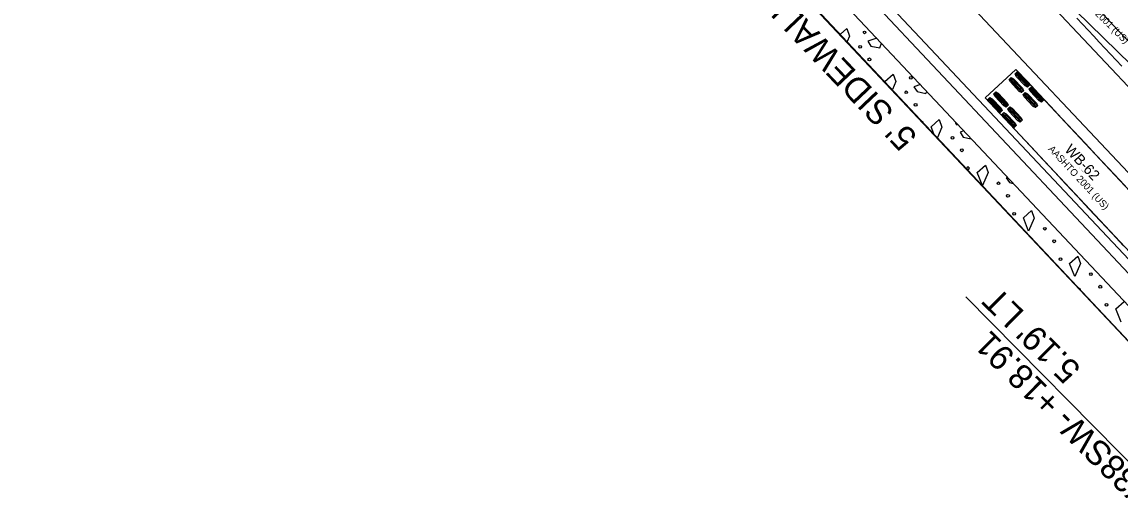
# Model space of a CAD drawing. Extents: x 1262642 to 1268358, y 767825 to 773481.
# Drawn here: x 1266385.4 to 1266608.5, y 772120.2 to 772219.4 of the extents above; entities that cross this region are included whole.
import ezdxf

# ---------------------------------------------------------------- set-up
doc = ezdxf.new("R2010")
doc.units = 0
for name, color, linetype in [('Prop Conc 2ft 6in Curb and Gutter', 7, 'Continuous'), ('Prop Conc 4in Sidewalk', 7, 'Continuous'), ('Prop Dimension Text', 7, 'Continuous'), ('Prop EOT', 7, 'Continuous'), ('Prop Horizontal Alignment', 7, 'Continuous'), ('Prop Lane Lines', 7, 'Continuous'), ('Prop Paved Shoulder', 7, 'Continuous'), ('Prop Shade Light', 7, 'Continuous'), ('Scratch_Level_3', 7, 'Continuous')]:
    doc.layers.add(name, color=color, linetype=linetype)

msp = doc.modelspace()

# ---------------------------------------------------------------- linework, layer by layer
at = {"layer": 'Prop Conc 2ft 6in Curb and Gutter'}
for p, q in [((1266506.17, 772278.96), (1266647.88, 772128.24)), ((1266502.71, 772276.07), (1266644.44, 772125.33)), ((1266497.36, 772274.9), (1266640.83, 772121.86)), ((1266551.72, 772216.91), (1266553.03, 772218.07)), ((1266553.03, 772218.07), (1266553.55, 772216.54)), ((1266553.55, 772216.54), (1266553.09, 772215.46)), ((1266559.09, 772216.11), (1266557.25, 772215.49)), ((1266557.25, 772215.49), (1266557.89, 772214.5)), ((1266559.7, 772214.13), (1266560.05, 772215.08)), ((1266557.89, 772214.5), (1266559.7, 772214.13)), ((1266560.72, 772207.33), (1266562.41, 772208.83)), ((1266562.41, 772208.83), (1266562.93, 772207.29)), ((1266560.74, 772207.3), (1266560.72, 772207.33)), ((1266562.93, 772207.29), (1266562.25, 772205.69)), ((1266567.94, 772206.69), (1266566.63, 772206.24)), ((1266566.63, 772206.24), (1266567.28, 772205.26)), ((1266567.28, 772205.26), (1266569.08, 772204.88)), ((1266569.08, 772204.88), (1266569.24, 772205.31)), ((1266570.11, 772198.08), (1266571.79, 772199.58)), ((1266571.79, 772199.58), (1266572.32, 772198.05)), ((1266570.66, 772196.71), (1266570.11, 772198.08)), ((1266572.32, 772198.05), (1266571.41, 772195.92)), ((1266576.8, 772197.26), (1266576.02, 772197)), ((1266576.02, 772197), (1266576.66, 772196.01)), ((1266576.66, 772196.01), (1266578.3, 772195.67)), ((1266579.49, 772188.84), (1266581.18, 772190.34)), ((1266581.18, 772190.34), (1266581.7, 772188.8)), ((1266580.57, 772186.16), (1266579.49, 772188.84)), ((1266581.7, 772188.8), (1266580.57, 772186.16)), ((1266585.66, 772187.84), (1266585.4, 772187.75)), ((1266585.4, 772187.75), (1266586.05, 772186.77)), ((1266586.05, 772186.77), (1266586.82, 772186.61)), ((1266588.87, 772179.59), (1266590.56, 772181.09)), ((1266589.95, 772176.91), (1266588.87, 772179.59)), ((1266591.08, 772179.56), (1266589.95, 772176.91)), ((1266590.56, 772181.09), (1266591.08, 772179.56)), ((1266598.26, 772170.35), (1266599.94, 772171.84)), ((1266599.34, 772167.67), (1266598.26, 772170.35)), ((1266600.47, 772170.31), (1266599.34, 772167.67)), ((1266599.94, 772171.84), (1266600.47, 772170.31)), ((1266607.64, 772161.1), (1266609.33, 772162.6)), ((1266608.72, 772158.42), (1266607.64, 772161.1))]:
    msp.add_line(p, q, dxfattribs=at)
for centre, radius in [((1266556.62, 772217.3), 0.268), ((1266555.69, 772214.37), 0.268), ((1266557.59, 772211.82), 0.292), ((1266566, 772208.06), 0.268), ((1266565.08, 772205.12), 0.268), ((1266566.98, 772202.57), 0.292), ((1266574.46, 772195.88), 0.268), ((1266576.36, 772193.33), 0.292), ((1266583.84, 772186.63), 0.268), ((1266585.75, 772184.08), 0.292), ((1266587.01, 772180.42), 0.268), ((1266593.23, 772177.39), 0.268), ((1266595.13, 772174.84), 0.292), ((1266596.4, 772171.18), 0.268), ((1266602.61, 772168.14), 0.268), ((1266604.51, 772165.59), 0.292), ((1266605.78, 772161.93), 0.268)]:
    msp.add_circle(centre, radius, dxfattribs=at)
for centre, radius, start, end in [((1266562.64, 772212.72), 0.289, 200.6053, 245.8613), ((1266568.25, 772198.91), 0.268, 25.7051, 60.5975), ((1266575.38, 772198.81), 0.268, 138.6088, 307.8579), ((1266577.63, 772189.67), 0.268, 230.5683, 215.7344), ((1266600.23, 772164.96), 0.268, 344.2878, 102.0149)]:
    msp.add_arc(centre, radius, start, end, dxfattribs=at)
at = {"layer": 'Prop Conc 4in Sidewalk'}
for p, q in [((1266502.44, 772276.36), (1266644.6, 772125.15)), ((1266498.39, 772273.36), (1266640.96, 772121.73))]:
    msp.add_line(p, q, dxfattribs=at)
at = {"layer": 'Prop Dimension Text'}
msp.add_line((1266577.15, 772163.56), (1266617.63, 772122.52), dxfattribs=at)
at = {"layer": 'Prop EOT'}
msp.add_line((1266507.71, 772280.24), (1266649.33, 772129.6), dxfattribs=at)
msp.add_arc((1266840.27, 772443.46), 318.09, 223.2333, 243.6532, dxfattribs=at)
at = {"layer": 'Prop Horizontal Alignment'}
msp.add_line((1266456.7, 772369.54), (1266660.64, 772152.62), dxfattribs=at)
at = {"layer": 'Prop Lane Lines'}
msp.add_line((1266516.45, 772288.46), (1266651.9, 772144.4), dxfattribs=at)
msp.add_arc((1275047.31, 780021.23), 11427, 216.367499, 223.547684, dxfattribs=at)
at = {"layer": 'Prop Paved Shoulder'}
msp.add_arc((1275047.31, 780021.23), 11449, 220.505091, 223.202447, dxfattribs=at)
at = {"layer": 'Prop Shade Light'}
msp.add_arc((1275047.31, 780021.23), 11449, 220.505091, 223.202447, dxfattribs=at)
at = {"layer": 'Scratch_Level_3'}
for p, q in [((1266584.3, 772236.71), (1266618.52, 772203.06)), ((1266587.35, 772209.79), (1266581.14, 772203.99)), ((1266588.88, 772205.4), (1266586.38, 772208.08)), ((1266589.75, 772206.22), (1266587.25, 772208.89)), ((1266620.13, 772174.72), (1266587.35, 772209.79)), ((1266589.92, 772206.37), (1266587.42, 772209.05)), ((1266590.09, 772206.53), (1266587.58, 772209.21)), ((1266588.55, 772205.09), (1266586.04, 772207.77)), ((1266588.72, 772205.25), (1266586.21, 772207.92)), ((1266592.6, 772203.17), (1266590.09, 772205.85)), ((1266592.77, 772203.33), (1266590.26, 772206.01)), ((1266592.93, 772203.48), (1266590.43, 772206.16)), ((1266581.14, 772203.99), (1266613.92, 772168.92)), ((1266584.21, 772201.04), (1266581.71, 772203.72)), ((1266584.38, 772201.19), (1266581.88, 772203.87)), ((1266584.55, 772201.35), (1266582.04, 772204.03)), ((1266585.42, 772202.16), (1266582.91, 772204.84)), ((1266585.59, 772202.32), (1266583.08, 772205)), ((1266585.75, 772202.48), (1266583.25, 772205.16)), ((1266591.39, 772202.04), (1266588.89, 772204.72)), ((1266591.56, 772202.2), (1266589.06, 772204.88)), ((1266591.73, 772202.36), (1266589.22, 772205.04)), ((1266588.26, 772199.12), (1266585.76, 772201.8)), ((1266588.43, 772199.28), (1266585.93, 772201.96)), ((1266588.6, 772199.43), (1266586.09, 772202.11)), ((1266587.06, 772197.99), (1266584.55, 772200.67)), ((1266587.23, 772198.15), (1266584.72, 772200.83)), ((1266587.39, 772198.31), (1266584.89, 772200.99))]:
    msp.add_line(p, q, dxfattribs=at)
for points in [[(1266608.85, 772210.42), (1266607.71, 772211.64), (1266606.57, 772212.86), (1266605.43, 772214.08), (1266604.3, 772215.3), (1266603.16, 772216.51), (1266602.02, 772217.73), (1266600.88, 772218.95), (1266599.75, 772220.17)], [(1266587.35, 772209.79), (1266589.69, 772207.29), (1266592.04, 772204.78), (1266594.38, 772202.28), (1266596.72, 772199.77), (1266599.06, 772197.27), (1266601.41, 772194.77), (1266603.75, 772192.27), (1266606.1, 772189.77), (1266608.45, 772187.27), (1266610.81, 772184.78)], [(1266581.14, 772203.99), (1266583.48, 772201.48), (1266585.83, 772198.98), (1266588.17, 772196.47), (1266590.51, 772193.97), (1266592.85, 772191.46), (1266595.19, 772188.96), (1266597.53, 772186.45), (1266599.87, 772183.95), (1266602.21, 772181.44), (1266604.55, 772178.94), (1266606.9, 772176.43), (1266609.24, 772173.93)]]:
    msp.add_lwpolyline(points, dxfattribs=at)
for points in [[(1266588.92, 772205.44), (1266588.51, 772205.05), (1266588.03, 772205.31), (1266586.23, 772207.24), (1266586, 772207.73), (1266586.42, 772208.12), (1266586.9, 772207.86), (1266588.7, 772205.93)], [(1266590.13, 772206.57), (1266589.71, 772206.18), (1266589.24, 772206.43), (1266587.43, 772208.36), (1266587.21, 772208.86), (1266587.63, 772209.25), (1266588.1, 772208.99), (1266589.91, 772207.06)], [(1266592.97, 772203.52), (1266592.56, 772203.13), (1266592.08, 772203.39), (1266590.28, 772205.32), (1266590.05, 772205.81), (1266590.47, 772206.2), (1266590.95, 772205.94), (1266592.75, 772204.02)], [(1266584.59, 772201.39), (1266584.17, 772201), (1266583.7, 772201.26), (1266581.89, 772203.18), (1266581.67, 772203.68), (1266582.09, 772204.07), (1266582.56, 772203.81), (1266584.36, 772201.88)], [(1266585.79, 772202.52), (1266585.38, 772202.13), (1266584.9, 772202.38), (1266583.1, 772204.31), (1266582.87, 772204.8), (1266583.29, 772205.19), (1266583.77, 772204.94), (1266585.57, 772203.01)], [(1266591.77, 772202.4), (1266591.35, 772202.01), (1266590.88, 772202.26), (1266589.07, 772204.19), (1266588.85, 772204.68), (1266589.27, 772205.08), (1266589.74, 772204.82), (1266591.54, 772202.89)], [(1266588.64, 772199.47), (1266588.22, 772199.08), (1266587.75, 772199.34), (1266585.94, 772201.27), (1266585.72, 772201.76), (1266586.14, 772202.15), (1266586.61, 772201.89), (1266588.42, 772199.96)], [(1266587.43, 772198.35), (1266587.02, 772197.95), (1266586.54, 772198.21), (1266584.74, 772200.14), (1266584.51, 772200.63), (1266584.93, 772201.02), (1266585.41, 772200.77), (1266587.21, 772198.84)]]:
    msp.add_lwpolyline(points, close=True, dxfattribs=at)
msp.add_arc((1271970.4, 777276.39), 7371.86, 222.967251, 223.613894, dxfattribs=at)

# ---------------------------------------------------------------- texts
at = {"layer": 'Prop Dimension Text'}
for s, rotation, p in [("5' SIDEWALK", 133.4955, (1266567.55, 772196.23)), ("5.19' LT", 135.4239, (1266600.81, 772149.04)), ('-Y38SW- +18.91', 135.4239, (1266617.47, 772122.09))]:
    msp.add_text(s, height=5, rotation=rotation, dxfattribs=at).set_placement(p)
at = {"layer": 'Scratch_Level_3'}
for s, height, rotation, p in [('AASHTO 2001 (US)', 1.4167, 315.4849, (1266597.43, 772226.77)), ('WB-62', 2.125, 313.0637, (1266597.13, 772193.35)), ('AASHTO 2001 (US)', 1.4167, 313.0637, (1266593.84, 772193.5)), ('(c) 2016 Transoft Solutions, Inc. All rights reserved.', 0.085, 313.0637, (1266599.42, 772190.59))]:
    msp.add_text(s, height=height, rotation=rotation, dxfattribs=at).set_placement(p)

doc.saveas('drawing.dxf')
